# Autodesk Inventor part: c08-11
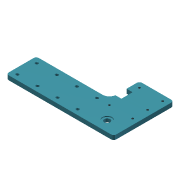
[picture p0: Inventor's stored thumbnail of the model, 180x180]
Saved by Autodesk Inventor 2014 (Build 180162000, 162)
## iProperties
Created: 2010-12
Part Number: c08-11
Material: Steel
Document SubType Name: Modeling
Designer: Thom Tremblay
Mass: 1769.34 g
Surface Area: 558.866 cm^2
Volume: 225.394 cm^3
Density: 7.85 g/cm^3
Appearance: Cadet Blue
Author: Thom Tremblay
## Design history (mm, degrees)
sketch "Sketch1"
  geometry: L1 (0, 0)-(250, 0); L2 (250, 0)-(250, 70); L3 (250, 70)-(0, 70); L4 (0, 70)-(0, 0); L5 (250, 70)-(170, 70); L6 (170, 70)-(170, 140); L7 (170, 140)-(250, 140); L8 (250, 140)-(250, 70)
  constraints: 16 end point, 4 parallel, 2 horizontal, 2 perpendicular
  dimensions: "d0" = 250 distance of L3.end L2.end; "d1" = 70 distance of L2.end L1.end; "d2" = 80 distance of L6.end L7.end; "d3" = 70 distance of L5.end L6.end
extrude "Extrusion1" new body sketch "Sketch1" distance "d4" = 10; taper "d5" = 0 deg
sketch "Sketch4"
  geometry: L1 (250, 140)-(170, 140) reference; L2 (170, 140)-(170, 70) reference; L3 (170, 84)-(184, 84); L4 (184, 84)-(184, 110); L5 (184, 110)-(170, 110); L6 (170, 110)-(170, 84)
  constraints: 8 end point, 2 parallel, 1 horizontal, 1 perpendicular, 1 point on line
  dimensions: "d41" = 14 distance of L5.end L4.end; "d42" = 26 distance of L4.end L3.end; "d43" = 30 distance between parallel lines of L1 L5
extrude "Extrusion2" cut sketch "Sketch4" stored distance "d44" = 10; taper "d45" = 0 deg
sketch "Sketch2"
  geometry: L1 (0, 70)-(0, 0) reference; L2 (14, 12.5)-(154, 12.5); L3 (154, 12.5)-(154, 57.5); L4 (154, 57.5)-(14, 57.5); L5 (14, 57.5)-(14, 12.5); L6 (60.667, 57.5)-(60.667, 12.5); L7 (107.333, 57.5)-(107.333, 12.5); 2 further points
  constraints: 12 end point, 4 point on line, 3 perpendicular, 2 midpoint, 2 parallel, 1 horizontal, 1 horizontal alignment
  dimensions: "d6" = 140 distance of L4.end L3.end; "d7" = 45 distance of L3.end L2.end; "d8" = 46.66667 distance between parallel lines of L6 L5 (= 0.333333 x d6); "d9" = 46.66667 distance between parallel lines of L7 L6 (= d8); "d10" = 14 distance between parallel lines of L1 L5
hole "Hole1" sketch "Sketch2" at (14, 12.5), (154, 57.5), (154, 12.5), (14, 57.5), (60.667, 57.5), (60.667, 12.5), (107.333, 57.5), (107.333, 12.5) diameter "d11" = 6.6; stored, may be unused: countersink angle "d15" = 90 deg, drill point angle "d17" = 118 deg; dims "d12" = 6, "d13" = 4, "d14" = 90, "d16" = 8
sketch "Sketch3"
  geometry: L1 (250, 0)-(250, 140) reference; L2 (250, 140)-(170, 140) reference; L3 (170, 140)-(170, 70) reference; L4 (0, 0)-(250, 0) reference; L5 (183, 127)-(237, 127); L6 (237, 127)-(237, 92); L7 (237, 92)-(237, 57); L8 (237, 57)-(183, 57)
  constraints: 8 end point, 2 equal length, 2 parallel, 1 collinear, 1 perpendicular
  dimensions: "d18" = 13 distance between parallel lines of L1 L6; "d19" = 13 distance from line of L3 L5.start (= d18); "d20" = 13 distance between parallel lines of L2 L5 (= d18); "d22" = 35 distance of L6.end L7.end
hole "Hole2" sketch "Sketch3" at (183, 127), (237, 127), (237, 92), (237, 57), (183, 57) diameter "d23" = 4.917; stored, may be unused: countersink angle "d27" = 90 deg, drill point angle "d29" = 118 deg; dims "d24" = 6, "d25" = 4, "d26" = 90, "d28" = 8
hole "Hole3" diameter "d32" = 13.492; stored, may be unused: countersink angle "d36" = 90 deg, drill point angle "d38" = 118 deg; dims "d30" = 40, "d31" = 25, "d33" = 6, "d34" = 22.225, "d35" = 2, "d37" = 8
fillet "Fillet1" dims "d39" = 6, "d46" = 1
fillet "Fillet2" dims "d40" = 16
chamfer "Chamfer1" distance "d47" = 0.5; stored, may be unused: second distance "d48" = 2, angle "d49" = 45 deg
hole "Hole4" diameter "d52" = 3.242; stored, may be unused: countersink angle "d56" = 90 deg, drill point angle "d58" = 118 deg; dims "d50" = 43, "d51" = 5, "d53" = 8, "d54" = 4, "d55" = 2, "d57" = 10
chamfer "Chamfer2" distance "d59" = 0.5; stored, may be unused: second distance "d60" = 2, angle "d61" = 45 deg
body "Solid1"
